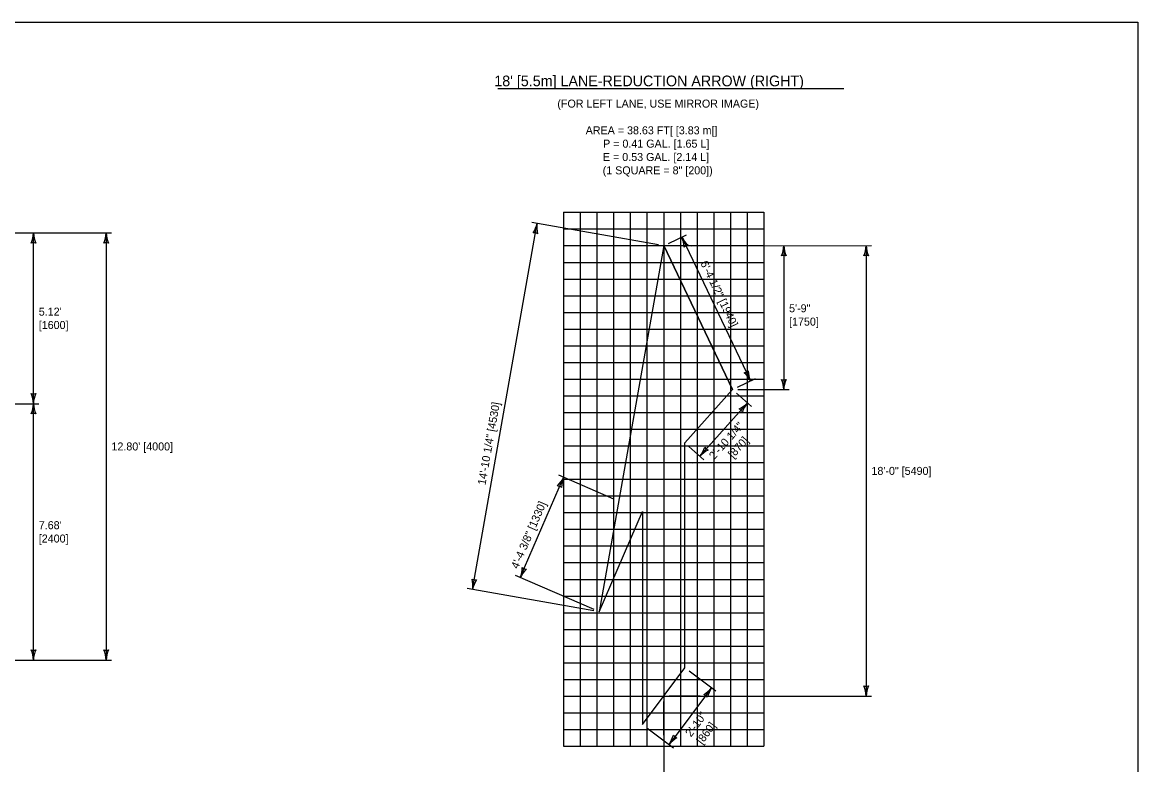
# Model space of a CAD drawing. Extents: x 49991.4 to 50021, y 49980.9 to 50011.4.
# Drawn here: x 50008.39 to 50016.75, y 49993.44 to 49999 of the extents above; entities that cross this region are included whole.
import ezdxf

# ---------------------------------------------------------------- set-up
doc = ezdxf.new("R2010")
doc.units = 0
for name, color, linetype in [('Level 1', 7, 'Continuous'), ('Level 2', 7, 'Continuous'), ('Level 3', 7, 'Continuous'), ('Level 9', 7, 'Continuous')]:
    doc.layers.add(name, color=color, linetype=linetype)

msp = doc.modelspace()

# ---------------------------------------------------------------- linework, layer by layer
at = {"layer": 'Level 1'}
for p, q in [((50013.1973, 49997.3258), (50012.7132, 49994.583)), ((50013.1973, 49997.3258), (50012.7132, 49994.583)), ((50013.1973, 49997.3258), (50013.7134, 49996.2477)), ((50013.7134, 49996.2477), (50013.1973, 49997.3258)), ((50013.3566, 49995.8488), (50013.7134, 49996.2477)), ((50013.3566, 49995.8488), (50013.7134, 49996.2477)), ((50013.3566, 49994.1633), (50013.3566, 49995.8488)), ((50013.3566, 49994.1633), (50013.3566, 49995.8488)), ((50012.7132, 49994.583), (50013.0379, 49995.3342)), ((50012.7132, 49994.583), (50013.0379, 49995.3342)), ((50013.0379, 49995.3342), (50013.0379, 49993.7383)), ((50013.0379, 49995.3342), (50013.0379, 49993.7383)), ((50013.0379, 49993.7383), (50013.3566, 49994.1633)), ((50013.0379, 49993.7383), (50013.3566, 49994.1633))]:
    msp.add_line(p, q, dxfattribs=at)
msp.add_lwpolyline([(49999.3835, 49998.9992), (50016.7501, 49998.9992), (50016.7501, 49987.7988), (49999.3835, 49987.7988)], close=True, dxfattribs=at)
at = {"layer": 'Level 2'}
msp.add_line((50011.9537, 49998.5042), (50014.5483, 49998.5042), dxfattribs=at)
at = {"layer": 'Level 3'}
for p, q in [((50011.7646, 49994.7504), (50012.2487, 49997.4932)), ((50013.1579, 49997.3327), (50012.2093, 49997.5001)), ((50007.7637, 49997.4214), (50009.0585, 49997.4214)), ((50008.4737, 49996.1414), (50008.4737, 49997.4214)), ((50009.0185, 49997.4214), (50009.0185, 49994.2214)), ((50013.2333, 49997.3431), (50013.3686, 49997.4078)), ((50013.3326, 49997.3906), (50013.8487, 49996.3124)), ((50013.2373, 49997.3258), (50013.3094, 49997.3258)), ((50013.4075, 49997.3257), (50014.7546, 49997.3258)), ((50014.0973, 49997.3258), (50014.0973, 49996.2477)), ((50014.7146, 49997.3258), (50014.7146, 49993.9508)), ((50013.7495, 49996.2649), (50013.8848, 49996.3297)), ((50013.7432, 49996.221), (50013.855, 49996.121)), ((50013.7534, 49996.2477), (50014.1373, 49996.2477)), ((50008.1637, 49996.1414), (50008.5137, 49996.1414)), ((50008.4737, 49994.2214), (50008.4737, 49996.1414)), ((50013.8252, 49996.1477), (50013.4684, 49995.7488)), ((50013.3865, 49995.8221), (50013.4983, 49995.7221)), ((50013.4126, 49995.6901), (50013.4126, 49995.6901)), ((50012.8227, 49995.4272), (50012.4105, 49995.6054)), ((50012.1225, 49994.8384), (50012.4472, 49995.5896)), ((50012.6765, 49994.5989), (50012.0858, 49994.8542)), ((50012.6738, 49994.59), (50011.7252, 49994.7574)), ((50008.1637, 49994.2214), (50009.0585, 49994.2214)), ((50013.3886, 49994.1393), (50013.5886, 49993.9893)), ((50013.5566, 49994.0133), (50013.2379, 49993.5883)), ((50013.4697, 49993.9508), (50013.2373, 49993.9508)), ((50013.5668, 49993.9507), (50014.7546, 49993.9508)), ((50013.0699, 49993.7143), (50013.2699, 49993.5643)), ((50013.1973, 49993.5788), (50013.1973, 49992.2485))]:
    msp.add_line(p, q, dxfattribs=at)
for points in [[(50013.1973, 49993.6587), (50013.1973, 49993.9108)], [(50013.1973, 49993.5788), (50013.1973, 49993.5787)]]:
    msp.add_lwpolyline(points, dxfattribs=at)
for centre, radius, start, end in [((50012.0315, 49997.5408), 0.2223, 327.44714, 347.63065), ((50012.4799, 49997.4641), 0.233, 172.81844, 192.06829), ((50008.2515, 49997.4305), 0.2223, 337.45601, 357.63952), ((50008.7064, 49997.4329), 0.233, 182.82731, 202.07716), ((50008.7963, 49997.4305), 0.2223, 337.45601, 357.63952), ((50009.2512, 49997.4329), 0.233, 182.82731, 202.07716), ((50012.2264, 49997.3669), 0.0548, 62.12995, 97.85231), ((50013.1283, 49997.3029), 0.2223, 3.039, 23.22251), ((50013.5375, 49997.5014), 0.233, 208.4103, 227.66015), ((50008.4737, 49997.2932), 0.0548, 72.13882, 107.86118), ((50009.0185, 49997.2932), 0.0548, 72.13882, 107.86118), ((50013.3879, 49997.2749), 0.0548, 97.72181, 133.44417), ((50013.8752, 49997.3349), 0.2223, 337.45601, 357.63952), ((50014.3301, 49997.3373), 0.233, 182.82731, 202.07716), ((50014.4925, 49997.3349), 0.2223, 337.45601, 357.63952), ((50014.9473, 49997.3373), 0.233, 182.82731, 202.07716), ((50014.0973, 49997.1976), 0.0548, 72.13882, 107.86118), ((50014.7146, 49997.1976), 0.0548, 72.13882, 107.86118), ((50013.7934, 49996.4281), 0.0548, 277.72181, 313.44417), ((50013.6438, 49996.2016), 0.233, 28.4103, 47.66015), ((50014.053, 49996.4001), 0.2223, 183.039, 203.22251), ((50014.0973, 49996.3759), 0.0548, 252.13882, 287.86118), ((50013.8646, 49996.2362), 0.233, 2.82731, 22.07716), ((50014.3195, 49996.2385), 0.2223, 157.45601, 177.63952), ((50008.4737, 49996.2696), 0.0548, 252.13882, 287.86118), ((50008.2409, 49996.1299), 0.233, 2.82731, 22.07716), ((50008.6958, 49996.1322), 0.2223, 157.45601, 177.63952), ((50008.2515, 49996.1505), 0.2223, 337.45601, 357.63952), ((50008.7064, 49996.1529), 0.233, 182.82731, 202.07716), ((50013.6658, 49996.3026), 0.2223, 295.6445, 315.82801), ((50013.7398, 49996.0521), 0.0548, 30.32731, 66.04967), ((50014.0063, 49996.0011), 0.233, 141.0158, 160.26565), ((50008.4737, 49996.0132), 0.0548, 72.13882, 107.86118), ((50013.2873, 49995.8954), 0.233, 321.0158, 340.26565), ((50013.6279, 49995.5939), 0.2223, 115.6445, 135.82801), ((50013.5539, 49995.8443), 0.0548, 210.32731, 246.04967), ((50012.2469, 49995.6861), 0.2223, 314.07789, 334.2614), ((50012.3963, 49995.4719), 0.0548, 48.7607, 84.48306), ((50012.6654, 49995.5078), 0.233, 159.44919, 178.69904), ((50011.9043, 49994.9202), 0.233, 339.44919, 358.69904), ((50012.3227, 49994.7418), 0.2223, 134.07789, 154.2614), ((50012.1734, 49994.9561), 0.0548, 228.7607, 264.48306), ((50011.7869, 49994.8767), 0.0548, 242.12995, 277.85231), ((50011.5335, 49994.7795), 0.233, 352.81844, 12.06829), ((50011.9818, 49994.7028), 0.2223, 147.44714, 167.63065), ((50008.4737, 49994.3496), 0.0548, 252.13882, 287.86118), ((50008.2409, 49994.2099), 0.233, 2.82731, 22.07716), ((50008.6958, 49994.2122), 0.2223, 157.45601, 177.63952), ((50009.0185, 49994.3496), 0.0548, 252.13882, 287.86118), ((50008.7858, 49994.2099), 0.233, 2.82731, 22.07716), ((50009.2406, 49994.2122), 0.2223, 157.45601, 177.63952), ((50013.3844, 49994.1539), 0.2223, 300.58586, 320.76936), ((50013.7497, 49993.8828), 0.233, 145.95716, 165.20701), ((50014.7146, 49994.079), 0.0548, 252.13882, 287.86118), ((50014.4819, 49993.9393), 0.233, 2.82731, 22.07716), ((50014.9368, 49993.9416), 0.2223, 157.45601, 177.63952), ((50013.4797, 49993.9107), 0.0548, 35.26866, 70.99102), ((50013.0448, 49993.7187), 0.233, 325.95716, 345.20701), ((50013.4101, 49993.4477), 0.2223, 120.58586, 140.76936), ((50013.3148, 49993.6909), 0.0548, 215.26866, 250.99102)]:
    msp.add_arc(centre, radius, start, end, dxfattribs=at)
at = {"layer": 'Level 9'}
for p, q in [((50012.4472, 49997.5758), (50012.4472, 49993.5758)), ((50012.4472, 49997.5758), (50013.9473, 49997.5758)), ((50012.5722, 49997.5758), (50012.5722, 49993.5758)), ((50012.6972, 49997.5758), (50012.6972, 49993.5758)), ((50012.8222, 49997.5758), (50012.8222, 49993.5758)), ((50012.9472, 49997.5758), (50012.9472, 49993.5758)), ((50013.0723, 49997.5758), (50013.0723, 49993.5758)), ((50013.1973, 49997.5758), (50013.1973, 49993.5758)), ((50013.3223, 49997.5758), (50013.3223, 49993.5758)), ((50013.4473, 49997.5758), (50013.4473, 49993.5758)), ((50013.5723, 49997.5758), (50013.5723, 49993.5758)), ((50013.6973, 49997.5758), (50013.6973, 49993.5758)), ((50013.8223, 49997.5758), (50013.8223, 49993.5758)), ((50013.9473, 49997.5758), (50013.9473, 49993.5758)), ((50012.4472, 49997.4508), (50013.9473, 49997.4508)), ((50012.4472, 49997.3258), (50013.9473, 49997.3258)), ((50012.4472, 49997.2008), (50013.9473, 49997.2008)), ((50012.4472, 49997.0758), (50013.9473, 49997.0758)), ((50012.4472, 49996.9508), (50013.9473, 49996.9508)), ((50012.4472, 49996.8258), (50013.9473, 49996.8258)), ((50012.4472, 49996.7008), (50013.9473, 49996.7008)), ((50012.4472, 49996.5758), (50013.9473, 49996.5758)), ((50012.4472, 49996.4508), (50013.9473, 49996.4508)), ((50012.4472, 49996.3258), (50013.9473, 49996.3258)), ((50012.4472, 49996.3258), (50013.9473, 49996.3258)), ((50012.4472, 49996.2008), (50013.9473, 49996.2008)), ((50012.4472, 49996.0758), (50013.9473, 49996.0758)), ((50012.4472, 49995.9508), (50013.9473, 49995.9508)), ((50012.4472, 49995.8258), (50013.9473, 49995.8258)), ((50012.4472, 49995.7008), (50013.9473, 49995.7008)), ((50012.4472, 49995.5758), (50013.9473, 49995.5758)), ((50012.4472, 49995.4508), (50013.9473, 49995.4508)), ((50012.4472, 49995.3258), (50013.9473, 49995.3258)), ((50012.4472, 49995.2008), (50013.9473, 49995.2008)), ((50012.4472, 49995.0758), (50013.9473, 49995.0758)), ((50012.4472, 49994.9508), (50013.9473, 49994.9508)), ((50012.4472, 49994.8258), (50013.9473, 49994.8258)), ((50012.4472, 49994.7008), (50013.9473, 49994.7008)), ((50012.4472, 49994.5758), (50013.9473, 49994.5758)), ((50012.4472, 49994.4508), (50013.9473, 49994.4508)), ((50012.4472, 49994.3258), (50013.9473, 49994.3258)), ((50012.4472, 49994.2008), (50013.9473, 49994.2008)), ((50012.4472, 49994.0758), (50013.9473, 49994.0758)), ((50012.4472, 49993.9508), (50013.9473, 49993.9508)), ((50012.4472, 49993.8258), (50013.9473, 49993.8258)), ((50012.4472, 49993.7008), (50013.9473, 49993.7008)), ((50012.4472, 49993.5758), (50013.9473, 49993.5758))]:
    msp.add_line(p, q, dxfattribs=at)

# ---------------------------------------------------------------- texts
at = {"layer": 'Level 2'}
for s, height, p in [("18' [5.5m] LANE-REDUCTION ARROW (RIGHT)", 0.08, (50011.9279, 49998.5201)), ('(FOR LEFT LANE, USE MIRROR IMAGE)', 0.06, (50012.4006, 49998.3601)), ('AREA = 38.63 FT[ [3.83 m[]', 0.06, (50012.6128, 49998.1601)), ('P = 0.41 GAL. [1.65 L]', 0.06, (50012.7432, 49998.0601)), ('E = 0.53 GAL. [2.14 L]', 0.06, (50012.742, 49997.9601)), ('(1 SQUARE = 8" [200])', 0.06, (50012.7404, 49997.8601)), ("5.12'", 0.06, (50008.5137, 49996.8014)), ('5\'-9"', 0.06, (50014.1373, 49996.8267)), ('[1750]', 0.06, (50014.1373, 49996.7267)), ('[1600]', 0.06, (50008.5137, 49996.7014)), ("12.80' [4000]", 0.06, (50009.0585, 49995.7914)), ('18\'-0" [5490]', 0.06, (50014.7546, 49995.6083)), ("7.68'", 0.06, (50008.5137, 49995.2014)), ('[2400]', 0.06, (50008.5137, 49995.1014))]:
    msp.add_text(s, height=height, dxfattribs=at).set_placement(p)
for s, rotation, p in [('6\'-4 1/2" [1940]', 295.58299, (50013.4704, 49997.1953)), ('14\'-10 1/4" [4530]', 79.99113, (50011.8615, 49995.5296)), ('2\'-10 1/4"', 48.18849, (50013.5756, 49995.7186)), (' [870]', 48.18849, (50013.704, 49995.7122)), ('4\'-4 3/8" [1330]', 66.62188, (50012.1054, 49994.8991)), ('2\'-10"', 53.12984, (50013.402, 49993.6405)), ('[860]', 53.12984, (50013.4851, 49993.5846))]:
    msp.add_text(s, height=0.06, rotation=rotation, dxfattribs=at).set_placement(p)

doc.saveas('drawing.dxf')
